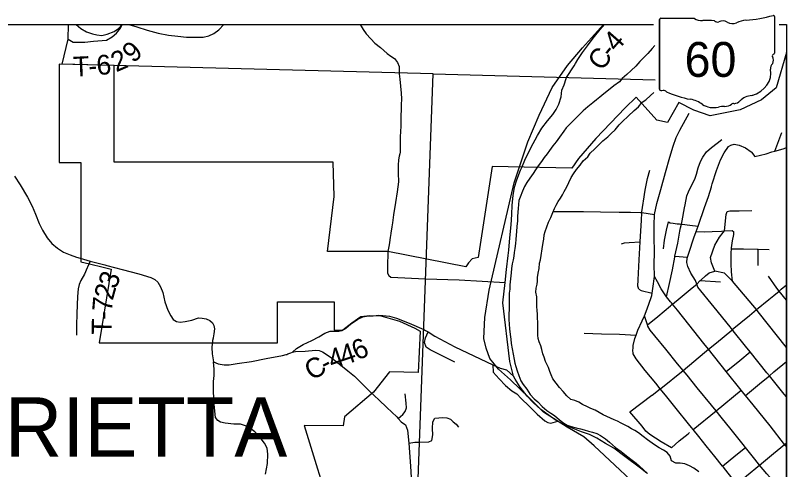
# Model space of a CAD drawing. Extents: x -84548 to 2262448, y -162180 to 525962.
# Drawn here: x 101301 to 112989, y 163944 to 170825 of the extents above; entities that cross this region are included whole.
import ezdxf

# ---------------------------------------------------------------- set-up
doc = ezdxf.new("R2010")
doc.units = 0
for name, color, linetype in [('GM_P_US_Location', 7, 'Continuous'), ('GM_X_County', 7, 'Continuous'), ('GM_X_County_Road', 7, 'Continuous'), ('GM_X_Hydro', 7, 'Continuous'), ('GM_X_Interstate_Location', 7, 'Continuous'), ('GM_X_Major_Lake_Text', 7, 'Continuous'), ('GM_X_Minor_Lake', 7, 'Continuous'), ('GM_X_Minor_River_Text', 7, 'Continuous'), ('GM_X_Rail_Line', 7, 'Continuous'), ('GM_X_Township_Road', 7, 'Continuous'), ('GM_X_Township_Subdivision_Text', 7, 'Continuous'), ('GM_X_Unincorporated_Location', 7, 'Continuous'), ('GM_X_US_Location', 7, 'Continuous')]:
    doc.layers.add(name, color=color, linetype=linetype)

msp = doc.modelspace()

# ---------------------------------------------------------------- linework, layer by layer
at = {"layer": 'GM_X_County'}
for p, q in [((77085, 170686), (110973, 170686)), ((112875, 170686), (112989, 170686)), ((112989, 170686), (112989, 134782))]:
    msp.add_line(p, q, dxfattribs=at)
at = {"layer": 'GM_X_Hydro'}
for p, q in [((102100, 170464), (102105, 170686)), ((102012, 170087), (102100, 170464)), ((107631, 169939), (102012, 170087)), ((107203, 158285), (107631, 169939)), ((107631, 169939), (110997, 169850))]:
    msp.add_line(p, q, dxfattribs=at)
at = {"layer": 'GM_X_Interstate_Location'}
for points in [[(110990, 170371), (110952, 170326), (110884, 170247), (110817, 170176), (110767, 170125), (110702, 170055), (110631, 169992), (110566, 169929), (110499, 169870), (110454, 169819), (110371, 169759), (110292, 169694), (110220, 169638), (110159, 169587), (110108, 169544), (110052, 169499)], [(109656, 168229), (109687, 168296), (109722, 168370), (109757, 168427), (109806, 168492), (109859, 168557), (109904, 168622), (109975, 168681), (110014, 168738), (110081, 168802), (110136, 168861), (110206, 168924), (110279, 168987), (110330, 169038), (110391, 169093), (110452, 169169), (110503, 169220), (110586, 169299), (110681, 169385), (110746, 169442), (110799, 169511), (110858, 169548), (110924, 169612), (110976, 169658)], [(110052, 169499), (109977, 169438), (109906, 169377), (109839, 169313), (109784, 169260), (109717, 169195), (109650, 169120), (109613, 169069), (109546, 168982), (109495, 168910), (109448, 168850), (109395, 168776), (109360, 168726), (109316, 168671), (109273, 168614), (109224, 168545), (109183, 168488), (109146, 168429), (109097, 168360), (109054, 168292), (109019, 168233), (108986, 168160), (108949, 168071), (108932, 168021), (108925, 167960), (108920, 167900), (108917, 167844), (108912, 167780), (108913, 167715), (108902, 167629), (108896, 167551), (108892, 167494), (108887, 167428), (108878, 167370), (108868, 167293), (108861, 167231), (108853, 167179), (108844, 167123), (108829, 167060), (108820, 166990), (108813, 166925), (108796, 166745), (108793, 166676), (108786, 166618), (108783, 166552), (108782, 166476), (108783, 166413), (108782, 166363), (108781, 166309), (108778, 166219), (108784, 166147), (108789, 166078), (108800, 165992), (108809, 165922), (108816, 165856), (108829, 165772), (108845, 165692), (108860, 165614), (108871, 165558), (108886, 165504), (108905, 165438), (108932, 165367), (108963, 165289), (108998, 165233), (109051, 165160), (109101, 165084), (109164, 165015), (109217, 164968), (109286, 164899), (109355, 164840), (109416, 164797), (109470, 164761), (109545, 164698), (109612, 164645), (109665, 164616), (109723, 164595), (109800, 164574), (109866, 164563), (109920, 164546), (109985, 164525), (110049, 164510), (110111, 164489), (110168, 164460), (110243, 164411), (110306, 164358), (110395, 164281), (110482, 164218), (110533, 164179), (110585, 164135), (110648, 164086), (110707, 164041), (110762, 163996), (110817, 163947), (110880, 163887)], [(111658, 163908), (111583, 163965), (111515, 164002), (111448, 164031), (111378, 164040), (111312, 164039), (111245, 164074), (111226, 164146), (111179, 164205), (111124, 164236), (111060, 164275), (111003, 164307), (110951, 164346), (110880, 164397), (110815, 164444), (110742, 164501), (110689, 164536), (110639, 164562), (110582, 164599), (110532, 164624), (110481, 164645), (110425, 164676), (110374, 164698), (110322, 164723), (110267, 164750), (110211, 164775), (110086, 164842), (110023, 164869), (109973, 164894), (109896, 164929), (109839, 164966), (109779, 164989), (109721, 165004), (109660, 165063), (109601, 165125), (109546, 165188), (109498, 165253), (109447, 165321), (109422, 165380), (109402, 165432), (109379, 165492), (109337, 165580), (109316, 165646), (109297, 165697), (109278, 165761), (109263, 165817), (109238, 165879), (109223, 165931), (109219, 165981), (109219, 166055), (109220, 166124), (109220, 166178), (109215, 166240), (109214, 166300), (109207, 166354), (109204, 166416), (109202, 166559), (109190, 166631), (109191, 166693), (109210, 166751), (109214, 166801), (109215, 166854), (109226, 166920), (109239, 166990), (109246, 167069), (109257, 167121), (109268, 167188), (109282, 167288), (109299, 167385), (109308, 167435), (109317, 167501), (109332, 167552), (109353, 167622), (109382, 167693), (109417, 167762), (109448, 167840), (109469, 167899), (109498, 167950), (109525, 168004), (109560, 168055), (109592, 168108), (109617, 168158), (109656, 168229)]]:
    msp.add_lwpolyline(points, dxfattribs=at)
at = {"layer": 'GM_X_Major_Lake_Text'}
msp.add_line((112958, 164324), (112989, 164286), dxfattribs=at)
for points in [[(111231, 166485), (111171, 166561), (111088, 166681), (111031, 166787), (110986, 166871), (110981, 167051), (110985, 167239), (110981, 167472), (110984, 167646), (110989, 167811), (111024, 167975), (111084, 168190), (111152, 168445), (111220, 168675), (111271, 168844), (111316, 168977), (111369, 169089), (111511, 169344)], [(101287, 168392), (101372, 168258), (101484, 168072), (101553, 167935), (101606, 167813), (101663, 167673), (101710, 167569), (101782, 167454), (101855, 167370), (101938, 167297), (102030, 167237), (102129, 167196), (102227, 167163), (102247, 167157), (102331, 167131)], [(102331, 167131), (102434, 167100), (102654, 167046), (102688, 167037)], [(102688, 167037), (102689, 167036), (102919, 166976), (103170, 166909), (103356, 166853), (103415, 166823), (103461, 166781), (103500, 166714), (103536, 166626), (103567, 166488), (103612, 166360), (103655, 166274), (103691, 166220), (103744, 166189), (103800, 166177), (103874, 166186), (103974, 166210), (104076, 166245), (104134, 166240), (104192, 166228), (104248, 166201), (104286, 166165), (104307, 166129), (104317, 166077), (104310, 166003), (104298, 165940), (104298, 165937)], [(112361, 165073), (112301, 165148), (112075, 165431), (111806, 165768), (111737, 165855), (111508, 166140), (111334, 166359), (111259, 166451), (111243, 166470), (111239, 166474), (111231, 166485)], [(104298, 165937), (104290, 165898), (104279, 165796), (104282, 165698), (104303, 165574), (104373, 165547), (104465, 165531), (104540, 165530), (104661, 165553), (104881, 165582), (105103, 165626), (105347, 165672), (105406, 165687)], [(105406, 165687), (105413, 165689), (105431, 165696), (105473, 165713), (105502, 165721), (105545, 165732), (105693, 165739), (105849, 165752), (105903, 165746), (105955, 165727), (106009, 165693), (106092, 165638), (106185, 165566), (106340, 165441), (106438, 165358), (106543, 165259), (106657, 165142)], [(106657, 165142), (106666, 165133), (106676, 165121), (106811, 165002), (106930, 164887), (107080, 164744), (107101, 164719), (107146, 164668), (107212, 164620), (107243, 164540), (107265, 164344), (107288, 163998), (107301, 163826)], [(112958, 164324), (112739, 164607), (112482, 164925), (112366, 165068), (112361, 165073)], [(111563, 163170), (111609, 163207), (111637, 163231), (111806, 163368), (111979, 163510), (112186, 163679), (112235, 163721), (112383, 163847), (112580, 164012), (112792, 164187), (112958, 164324)]]:
    msp.add_lwpolyline(points, dxfattribs=at)
at = {"layer": 'GM_X_Minor_Lake'}
for points in [[(102100, 170464), (102176, 170419), (102259, 170418), (102354, 170422), (102486, 170433), (102682, 170448), (102768, 170502), (102835, 170558), (102896, 170631), (102920, 170686)], [(102222, 170686), (102294, 170627), (102379, 170575), (102472, 170548), (102535, 170529), (102613, 170521), (102691, 170540), (102799, 170579), (102863, 170625), (102919, 170686)], [(103019, 170686), (103139, 170652), (103299, 170603), (103466, 170557), (103622, 170528), (103763, 170511), (103895, 170496), (104043, 170497), (104147, 170497), (104233, 170517), (104308, 170553), (104383, 170606), (104461, 170686)], [(106527, 170686), (106570, 170611), (106619, 170546), (106687, 170471), (106750, 170404), (106834, 170340), (106934, 170250), (106991, 170210), (107044, 170174), (107094, 170112), (107118, 170050), (107117, 169953), (107118, 169938)], [(107118, 169938), (107125, 169859), (107149, 169647), (107151, 169561), (107147, 169469), (107145, 169376), (107144, 169327), (107142, 169146), (107133, 168984), (107133, 168880), (107133, 168806), (107132, 168752), (107127, 168727)], [(107127, 168727), (107119, 168695), (107108, 168635), (107100, 168557), (107103, 168434), (107108, 168306), (107087, 168152), (107064, 167991), (107032, 167802), (107015, 167682)], [(107015, 167682), (107006, 167621), (106991, 167525)], [(106991, 167525), (106985, 167486), (106982, 167464), (106977, 167421)], [(102434, 167100), (102395, 167010), (102390, 166999)], [(102390, 166999), (102349, 166903), (102295, 166810), (102265, 166749), (102250, 166685), (102243, 166566), (102239, 166440), (102230, 166302), (102228, 166133), (102229, 165983)]]:
    msp.add_lwpolyline(points, dxfattribs=at)
at = {"layer": 'GM_X_Minor_River_Text'}
for points in [[(109792, 170098), (109825, 170157), (109895, 170261), (109969, 170366), (110058, 170478), (110162, 170611), (110227, 170686)], [(109649, 169868), (109655, 169886), (109771, 170062), (109790, 170095), (109792, 170098)], [(108975, 168522), (109023, 168631), (109113, 168820), (109212, 169006), (109277, 169116), (109363, 169228), (109447, 169326), (109495, 169399), (109536, 169480), (109571, 169593), (109585, 169693), (109617, 169773), (109649, 169868)], [(105502, 165721), (105563, 165777), (105662, 165840), (105793, 165899), (105898, 165955), (105990, 166009), (106074, 166039), (106136, 166042), (106202, 166039), (106248, 166052), (106307, 166088), (106382, 166145), (106492, 166224), (106569, 166260), (106647, 166275), (106721, 166273), (106807, 166286), (106868, 166281), (106973, 166266), (107079, 166239), (107268, 166161), (107489, 166064), (107515, 166052)], [(104313, 165369), (104315, 165386), (104315, 165465), (104303, 165574)], [(105092, 163876), (105121, 164037), (105128, 164178), (105116, 164268), (105078, 164343), (105012, 164428), (104930, 164514), (104849, 164576), (104788, 164607), (104712, 164630), (104609, 164633), (104479, 164645), (104409, 164663), (104368, 164690), (104333, 164732), (104323, 164828), (104308, 164992), (104302, 165168), (104305, 165280), (104313, 165369)]]:
    msp.add_lwpolyline(points, dxfattribs=at)
at = {"layer": 'GM_X_Rail_Line'}
for p, q in [((111065, 170762), (111065, 169706)), ((111065, 169706), (111065, 170762)), ((111065, 169706), (111065, 170762)), ((111082, 170781), (111592, 170781)), ((112806, 170807), (112806, 170254)), ((112805, 170254), (112806, 170254))]:
    msp.add_line(p, q, dxfattribs=at)
for centre, major_axis, start_param, end_param in [((111085, 170765), (20.2, 0), 1.712693, 3.28349), ((111713, 170903), (196, 0), 4.042523, 4.731795), ((111778, 170187), (702, 0), 1.404758, 1.657858), ((112421, 170458), (371, 0), 1.699011, 2.107814), ((112186, 172221), (1845, 0), 4.814394, 5.042369), ((112786, 170809), (19.4, 0), 6.141152, 7.989035), ((111938, 170770), (56.4, 0), 3.836095, 5.185415), ((112020, 170648), (117, 0), 0.950623, 2.079405), ((112172, 170815), (141, 0), 4.081561, 5.145723), ((112801, 170213), (30, 0), 1.883978, 3.671073), ((112610, 170144), (180, 0), 5.934695, 6.695948), ((112785, 170252), (20.7, 0), 5.05454, 6.418171), ((112875, 170023), (131, 0), 2.387724, 3.262537), ((112289, 169952), (462, 0), 5.101752, 6.440018), ((111085, 169703), (20.3, 0), 3.00124, 4.508301), ((111089, 169812), (155, 0), 4.665946, 4.897461), ((111120, 169645), (56, 0), 0.519207, 1.627899), ((111827, 170594), (1333, 0), 4.195997, 4.488961), ((112484, 169409), (253, 0), 1.647645, 2.488434), ((111430, 169231), (417, 0), 0.823519, 1.323587), ((111881, 169640), (265, 0), 4.026481, 4.996735), ((112053, 169560), (141, 0), 4.691044, 5.507374), ((112180, 169458), (39.7, 0), 1.147584, 2.315152), ((112163, 169603), (149, 0), 4.937069, 5.64225), ((112033, 169274), (217, 0), 1.495662, 1.94098)]:
    msp.add_ellipse(centre, major_axis=major_axis, ratio=0.8, start_param=start_param, end_param=end_param, dxfattribs=at)
at = {"layer": 'GM_X_Township_Subdivision_Text'}
msp.add_lwpolyline([(112989, 158999), (112989, 170264), (112831, 169730), (112608, 169545), (112283, 169395), (111832, 169303), (111585, 169390), (111355, 169505), (111183, 169201), (111020, 169238), (110707, 169586), (110544, 169423), (110099, 168962), (109834, 168657), (109734, 168509), (108529, 168536), (108315, 167156), (108223, 167135), (108166, 167077), (108130, 167015), (106945, 167248), (106030, 167248), (106133, 168080), (106115, 168601), (102797, 168601), (102798, 170066), (101962, 170088), (101962, 168597), (102292, 168597), (102292, 167091), (102423, 167059), (102629, 167011), (102750, 166982), (102572, 165863), (105272, 165863), (105272, 166484), (106130, 166484), (106130, 166054), (106261, 166059), (106401, 166167), (106538, 166264), (106672, 166281), (106838, 166275), (107122, 166195), (107354, 166085), (107433, 166039), (107406, 165413), (106973, 165424), (106727, 165119), (106287, 164742), (106268, 164608), (105676, 164611), (106106, 163218)], dxfattribs=at)
at = {"layer": 'GM_X_Unincorporated_Location'}
msp.add_lwpolyline([(110937, 163497), (110071, 164304), (109915, 164439), (109662, 164586), (109304, 164815), (109087, 165033), (108805, 165302), (108624, 165463), (108493, 165629), (108438, 165783), (108399, 165931), (108417, 166248), (108479, 166660), (108858, 168287), (109068, 168908), (109240, 169312), (109438, 169734), (109667, 170066), (109894, 170334), (110212, 170686)], dxfattribs=at)
at = {"layer": 'GM_X_US_Location'}
msp.add_line((112958, 164324), (112989, 164350), dxfattribs=at)
for points in [[(112813, 168768), (112919, 169052)], [(111500, 168152), (111500, 168152), (111539, 168227), (111596, 168342), (111621, 168420), (111648, 168515), (111685, 168613), (111721, 168678), (111776, 168756), (111853, 168825), (111937, 168892), (112006, 168943)], [(111849, 168230), (111849, 168231), (111861, 168273), (111927, 168474), (111988, 168635), (112043, 168742), (112110, 168837), (112144, 168859), (112194, 168874), (112270, 168860), (112364, 168817), (112453, 168758), (112456, 168755)], [(112679, 168730), (112764, 168758), (112813, 168768), (112868, 168781), (112950, 168808), (112989, 168823)], [(112456, 168755), (112510, 168686), (112679, 168730)], [(108770, 167189), (108779, 167270), (108795, 167455), (108814, 167653), (108823, 167808), (108832, 167952), (108845, 168099), (108866, 168223), (108902, 168336), (108957, 168482), (108970, 168512), (108975, 168522)], [(110814, 167980), (110819, 168012), (110843, 168176), (110882, 168355), (110916, 168481)], [(111629, 166752), (111608, 166808), (111537, 166919), (111490, 167023), (111477, 167081), (111482, 167145), (111488, 167163), (111510, 167238), (111585, 167457), (111619, 167552), (111647, 167632), (111652, 167646), (111745, 167913), (111805, 168080), (111849, 168230)], [(111453, 167955), (111479, 168090), (111500, 168152)], [(110750, 166676), (110736, 166722), (110741, 166821), (110756, 167123), (110769, 167394), (110769, 167400), (110788, 167719), (110794, 167839), (110795, 167847), (110814, 167979), (110814, 167980)], [(111382, 167606), (111382, 167607), (111394, 167663), (111404, 167713), (111444, 167909), (111453, 167955), (111453, 167955)], [(109446, 167854), (109670, 167854), (109912, 167853), (110170, 167849), (110451, 167844), (110625, 167843), (110777, 167839), (110778, 167839)], [(110778, 167839), (110794, 167839), (110989, 167811)], [(112029, 167538), (112048, 167563), (112048, 167563), (112075, 167809), (112089, 167854)], [(112089, 167854), (112129, 167864), (112271, 167865), (112463, 167869)], [(111122, 167287), (111140, 167418), (111171, 167573), (111200, 167699)], [(111171, 166561), (111214, 166761), (111258, 166968), (111294, 167161), (111297, 167178), (111338, 167373), (111372, 167556), (111382, 167606)], [(111200, 167699), (111222, 167683), (111271, 167675), (111329, 167668), (111364, 167665), (111365, 167665)], [(111365, 167665), (111394, 167663), (111405, 167663), (111523, 167646), (111647, 167632)], [(111619, 167552), (111742, 167548), (111862, 167553), (112002, 167558), (112048, 167563), (112166, 167566), (112190, 167546)], [(111900, 166948), (111852, 167075), (111835, 167155), (111902, 167346), (111973, 167466), (112028, 167537), (112029, 167538)], [(112150, 167228), (112152, 167287), (112153, 167305), (112167, 167411), (112191, 167506), (112190, 167546)], [(106977, 167421), (106968, 167350), (106945, 167248), (106942, 167015), (106941, 166919), (106959, 166883), (106991, 166859), (107517, 166833), (108028, 166818), (108724, 166779)], [(110489, 167363), (110531, 167378), (110605, 167384), (110769, 167394)], [(112152, 167287), (112335, 167287), (112545, 167281), (112557, 167281), (112723, 167279)], [(112559, 167034), (112557, 167281)], [(108746, 166974), (108770, 167189)], [(111297, 167178), (111488, 167163)], [(112171, 166800), (112156, 166938), (112149, 167059), (112150, 167199), (112150, 167227), (112150, 167228)], [(110675, 164040), (110674, 164041), (110661, 164051), (110515, 164156), (110370, 164267), (110246, 164340), (110115, 164420), (110000, 164473), (109883, 164517), (109755, 164566), (109604, 164631), (109521, 164675), (109499, 164687), (109377, 164771), (109265, 164854), (109147, 164962), (109058, 165056), (108951, 165194), (108877, 165313), (108848, 165360), (108793, 165582), (108690, 166470), (108724, 166779), (108746, 166974)], [(111610, 166737), (111629, 166752), (111680, 166808), (111687, 166816), (111759, 166882), (111814, 166925), (111900, 166948)], [(112558, 166336), (112533, 166368), (112531, 166370), (112171, 166800), (112049, 166918), (111900, 166948)], [(110945, 166584), (110951, 166618), (110962, 166686), (110986, 166871)], [(111680, 166808), (111988, 166789)], [(112841, 166694), (112841, 166695), (112715, 166872)], [(110750, 166676), (110787, 166655), (110951, 166618)], [(111243, 166439), (111245, 166440), (111259, 166451), (111374, 166546), (111529, 166674), (111609, 166736), (111610, 166737)], [(112178, 166050), (112166, 166065), (112134, 166105), (111892, 166404), (111645, 166706), (111629, 166752)], [(112795, 166583), (112795, 166583), (112874, 166648), (112907, 166675), (112989, 166744)], [(112989, 166510), (112874, 166648), (112841, 166694)], [(110833, 166273), (110863, 166341), (110902, 166452), (110941, 166564), (110945, 166584)], [(112426, 166280), (112463, 166310), (112533, 166368), (112721, 166521), (112795, 166583)], [(110879, 166138), (111036, 166264), (111229, 166427), (111243, 166439)], [(112989, 165794), (112559, 166334), (112558, 166336)], [(110665, 165701), (110659, 165755), (110662, 165782), (110666, 165825), (110688, 165931), (110707, 165983), (110735, 166056), (110800, 166198), (110833, 166273)], [(112989, 163522), (112822, 163723), (112764, 163793), (112691, 163882), (112580, 164012), (112509, 164104), (112366, 164281), (112352, 164299), (112148, 164552), (111995, 164739), (111919, 164834), (111851, 164919), (111635, 165180), (111480, 165373), (111419, 165447), (111337, 165547), (111157, 165770), (110991, 165969), (110923, 166057), (110886, 166117), (110879, 166138), (110833, 166273)], [(110950, 165072), (111075, 165167), (111083, 165173), (111419, 165447), (111746, 165718), (111806, 165768), (111925, 165866), (112157, 166057), (112166, 166065), (112426, 166280), (112426, 166280)], [(107586, 165759), (107525, 165800), (107503, 165867), (107515, 165938), (107559, 166031)], [(107515, 166052), (107559, 166031), (107660, 165965), (107962, 165805), (108536, 165531), (108646, 165482), (108742, 165455), (108848, 165360)], [(109921, 166009), (110183, 166002), (110455, 165994), (110707, 165983)], [(112989, 165045), (112953, 165089), (112728, 165366), (112691, 165411), (112437, 165728), (112367, 165815), (112180, 166048), (112178, 166050)], [(107962, 165572), (107586, 165759)], [(112075, 165431), (112280, 165599), (112437, 165728)], [(111548, 164579), (111501, 164636), (111313, 164871), (111152, 165069), (111075, 165167), (111009, 165252), (110847, 165447), (110710, 165623), (110665, 165697), (110665, 165701)], [(108536, 165531), (108543, 165419), (108633, 165318), (108730, 165219), (108827, 165139), (108899, 165090), (108968, 165020), (109085, 164903), (109208, 164784), (109326, 164681), (109372, 164656), (109414, 164648), (109521, 164675)], [(112366, 165068), (112607, 165266), (112728, 165366), (112797, 165424), (112989, 165580)], [(111571, 164550), (111919, 164834), (112301, 165148)], [(107101, 164719), (107173, 164778), (107206, 164825), (107228, 164879), (107225, 164951), (107206, 165091)], [(110611, 164818), (110948, 165071), (110950, 165072)], [(111244, 164275), (111089, 164363), (110916, 164474), (110854, 164527), (110799, 164601), (110611, 164818)], [(107614, 164387), (107625, 164468), (107624, 164565), (107627, 164666), (107658, 164723)], [(107658, 164723), (107779, 164733), (107842, 164726), (107893, 164707), (107934, 164667), (107980, 164630), (108015, 164587)], [(112235, 163721), (112194, 163773), (112032, 163978), (112016, 163998), (111899, 164142), (111768, 164303), (111659, 164443), (111571, 164550), (111548, 164579)], [(111244, 164275), (111361, 164378), (111495, 164487), (111518, 164505)], [(107265, 164344), (107355, 164357), (107426, 164357), (107568, 164366), (107614, 164387)], [(112016, 163998), (112218, 164162), (112366, 164281)], [(110873, 163889), (110777, 163965), (110675, 164040)]]:
    msp.add_lwpolyline(points, dxfattribs=at)

# ---------------------------------------------------------------- texts
at = {"layer": 'GM_P_US_Location'}
msp.add_text('MARIETTA', height=900, rotation=0, dxfattribs=at).set_placement((99337, 164138))
at = {"layer": 'GM_X_County_Road'}
for s, rotation, p in [('4', 48.843, (110410, 170260)), ('C', 53.9644, (110193, 169969)), ('-', 51.6268, (110336, 170166)), ('4', 18.6225, (106275, 165520)), ('6', 24.4186, (106481, 165591)), ('4', 19.3006, (106101, 165459)), ('C', 30.3416, (105793, 165285)), ('-', 27.0049, (106001, 165407))]:
    msp.add_text(s, height=300, rotation=rotation, dxfattribs=at).set_placement(p)
at = {"layer": 'GM_X_Rail_Line'}
msp.add_text('60', height=528, dxfattribs=at).set_placement((111443, 169894))
at = {"layer": 'GM_X_Township_Road'}
for s, rotation, p in [('9', 42.276, (103088, 170092)), ('2', 23.4365, (102828, 169961)), ('T', 2.6281, (102182, 169898)), ('6', 4.9715, (102542, 169919)), ('-', 4.3267, (102416, 169909)), ('3', 68.3445, (102822, 166666)), ('2', 74.5393, (102775, 166496)), ('7', 85.447, (102763, 166327)), ('-', 88.3839, (102760, 166208)), ('T', 89.0485, (102756, 165984))]:
    msp.add_text(s, height=300, rotation=rotation, dxfattribs=at).set_placement(p)

doc.saveas('drawing.dxf')
